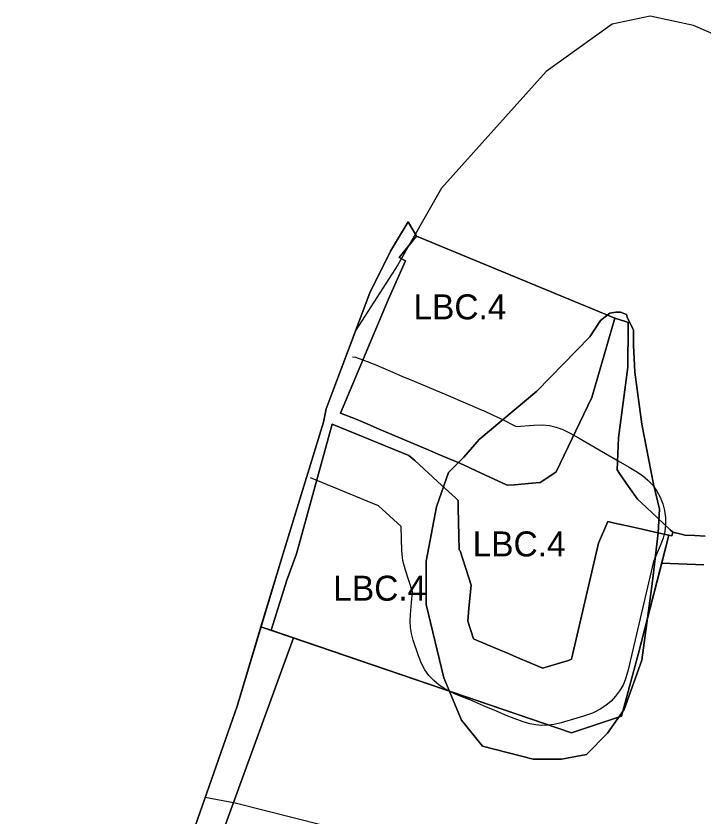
# Model space of a CAD drawing. Extents: x -555426 to -553015, y -1186745 to -1182595.
# Drawn here: x -555425.5 to -555067.9, y -1186406.3 to -1185990.3 of the extents above; entities that cross this region are included whole.
import ezdxf

# ---------------------------------------------------------------- set-up
doc = ezdxf.new("R2010")
doc.units = 0
for name, color, linetype in [('Level 12', 7, 'Continuous'), ('Level 14', 7, 'Continuous'), ('Level 7', 7, 'Continuous'), ('svahove_deformace', 7, 'Continuous'), ('USES_ID', 7, 'Continuous'), ('USES_LBC_navrh', 7, 'Continuous'), ('USES_LBC_stav', 7, 'Continuous'), ('USES_LBK_navrh', 7, 'Continuous')]:
    doc.layers.add(name, color=color, linetype=linetype)

msp = doc.modelspace()

# ---------------------------------------------------------------- linework, layer by layer
at = {"layer": 'Level 12'}
for points in [[(-555067.24, -1186260.4), (-555072.69, -1186260.16), (-555077.96, -1186259.94), (-555079.09, -1186259.62), (-555084.2, -1186258.4)], [(-555089.85, -1186274.46), (-555067.93, -1186275.38)], [(-555298.22, -1186307.56), (-555310.66, -1186348.84), (-555332.46, -1186411.11), (-555344.77, -1186450.74), (-555365.28, -1186506.04), (-555374.35, -1186523.58), (-555377.44, -1186522.92), (-555378.76, -1186526.22), (-555403.3, -1186597.68), (-555414.63, -1186645.4), (-555420.53, -1186680.78), (-555425.54, -1186725.43), (-555420.84, -1186723.67)], [(-555420.84, -1186723.67), (-555415.22, -1186721.67), (-555409.6, -1186719.66), (-555398.08, -1186648.64), (-555385.52, -1186601.65), (-555360.47, -1186527.99), (-555332.87, -1186455.38), (-555317.95, -1186413.97), (-555281.22, -1186313.35)]]:
    msp.add_lwpolyline(points, dxfattribs=at)
at = {"layer": 'Level 14'}
msp.add_lwpolyline([(-555298.22, -1186307.56), (-555136.76, -1186362.59), (-555110.73, -1186353.98), (-555101.91, -1186321.23), (-555086.13, -1186260.01), (-555084.7, -1186260.33), (-555084.2, -1186258.4), (-555085.48, -1186257.19), (-555091.92, -1186251.14), (-555097.77, -1186245.64), (-555102.5, -1186241.2), (-555107.16, -1186234.67), (-555111.88, -1186227.84), (-555113.1, -1186226.08), (-555112.35, -1186209.4), (-555107.58, -1186172.76), (-555107.3, -1186151.46), (-555107.27, -1186149.53), (-555108.76, -1186149.02), (-555114.26, -1186147.16), (-555217.36, -1186104.58), (-555221.63, -1186097.28), (-555227.21, -1186106.32), (-555230.94, -1186112.37), (-555241.55, -1186134.03), (-555264.37, -1186194.41), (-555265.72, -1186201.29), (-555286.2, -1186267.7), (-555298.22, -1186307.56)], dxfattribs=at)
at = {"layer": 'Level 7'}
msp.add_lwpolyline([(-555250.72, -1186167.24), (-555249.15, -1186167.56), (-555245.2, -1186168.87), (-555237.72, -1186171.87), (-555236.91, -1186172.21), (-555230.96, -1186174.74), (-555225.01, -1186177.29), (-555218.56, -1186179.99), (-555200.86, -1186187.48), (-555191.99, -1186191.24), (-555183.28, -1186194.95), (-555182.15, -1186195.45), (-555177.47, -1186197.61), (-555173.71, -1186199.35), (-555165.56, -1186203.42), (-555156.3, -1186202.74), (-555151.92, -1186202.63), (-555148.29, -1186202.98), (-555144.73, -1186203.77), (-555141.29, -1186205), (-555137.48, -1186206.9), (-555132.77, -1186209.62), (-555122.42, -1186215.62), (-555112.52, -1186221.34), (-555106.84, -1186224.63), (-555103.38, -1186226.63), (-555099.83, -1186228.99), (-555097.06, -1186231.36), (-555094.59, -1186234.04), (-555092.48, -1186237.01), (-555090.73, -1186240.22), (-555089.39, -1186243.61), (-555088.48, -1186247.14), (-555087.99, -1186250.75), (-555087.95, -1186254.4), (-555088.36, -1186258.03), (-555089.2, -1186261.57), (-555090.68, -1186265.57), (-555094.21, -1186273.57), (-555107.5, -1186330.65), (-555108.66, -1186334.57), (-555110.03, -1186337.79), (-555111.78, -1186340.82), (-555113.86, -1186343.64), (-555116.26, -1186346.19), (-555118.94, -1186348.44), (-555121.87, -1186350.36), (-555125.52, -1186352.2), (-555125.94, -1186352.37), (-555130.5, -1186354.02), (-555134.07, -1186355.06), (-555142.23, -1186357.46), (-555145.83, -1186358.32), (-555148.98, -1186358.72), (-555152.15, -1186358.79), (-555155.32, -1186358.52), (-555158.43, -1186357.92), (-555161.97, -1186356.83), (-555168.03, -1186354.62), (-555169.81, -1186353.92), (-555176.98, -1186350.9), (-555180.9, -1186349.26), (-555188.86, -1186345.9), (-555193.33, -1186344.02), (-555197.88, -1186342.11), (-555198.78, -1186341.73), (-555202.6, -1186339.84), (-555205.66, -1186337.83), (-555208.44, -1186335.47), (-555210.92, -1186332.79), (-555213.06, -1186329.82), (-555214.81, -1186326.62), (-555216.39, -1186322.66), (-555219.09, -1186314.48), (-555220.05, -1186310.97), (-555220.55, -1186307.89), (-555220.73, -1186304.78), (-555220.57, -1186301.14), (-555219.96, -1186294.94), (-555219.41, -1186289.33), (-555223.17, -1186278.1), (-555224.46, -1186273.05), (-555224.97, -1186268.08), (-555225.36, -1186255.41), (-555237.09, -1186244.63), (-555272.4, -1186230.19)], dxfattribs=at)
at = {"layer": 'svahove_deformace'}
for p, q in [((-555116.82, -1186144.7), (-555121.73, -1186148.37)), ((-555113.76, -1186144.08), (-555111.31, -1186144.08)), ((-555103.96, -1186175.33), (-555104.57, -1186161.24)), ((-555100.28, -1186202.29), (-555103.96, -1186175.33)), ((-555154.81, -1186185.14), (-555184.84, -1186210.26)), ((-555094.15, -1186233.54), (-555100.28, -1186202.29)), ((-555184.84, -1186210.26), (-555192.8, -1186219.45)), ((-555206.89, -1186245.18), (-555200.77, -1186227.41)), ((-555091.09, -1186246.41), (-555094.15, -1186233.54)), ((-555091.7, -1186258.66), (-555091.09, -1186246.41)), ((-555129.08, -1186373.85), (-555118.05, -1186362.82)), ((-555156.65, -1186376.3), (-555183, -1186369.56)), ((-555183, -1186369.56), (-555156.65, -1186376.3)), ((-555129.08, -1186373.85), (-555141.95, -1186376.3)), ((-555141.95, -1186376.3), (-555156.65, -1186376.3)), ((-555327.19, -1186396.06), (-555311.67, -1186398.97))]:
    msp.add_line(p, q, dxfattribs=at)
for points in [[(-554721.01, -1186449.83), (-554717.95, -1186390.39), (-554719.17, -1186364.05), (-554722.85, -1186353.02), (-554727.75, -1186346.28), (-554739.39, -1186334.64), (-554762.68, -1186319.93), (-554777.99, -1186296.65), (-554793.92, -1186260.5), (-554803.73, -1186229.86), (-554819.05, -1186205.36), (-554830.07, -1186186.97), (-554862.55, -1186143.47), (-554896.25, -1186093.23), (-554921.37, -1186069.33), (-554968.55, -1186046.05), (-555036.56, -1186011.13), (-555073.32, -1185995.19), (-555095.99, -1185990.29), (-555115.6, -1185994.58), (-555149.91, -1186019.09), (-555204.44, -1186079.75), (-555227.11, -1186119.58), (-555248.89, -1186153.45)], [(-555121.73, -1186148.37), (-555116.82, -1186144.7), (-555113.76, -1186144.08)], [(-555111.31, -1186144.08), (-555113.76, -1186144.08), (-555116.82, -1186144.7)], [(-555111.31, -1186144.08), (-555108.25, -1186145.31), (-555107.63, -1186147.15), (-555104.57, -1186153.27), (-555104.57, -1186161.24)], [(-555107.63, -1186147.15), (-555108.25, -1186145.31), (-555111.31, -1186144.08)], [(-555184.84, -1186210.26), (-555154.81, -1186185.14), (-555127.24, -1186156.95), (-555121.73, -1186148.37)], [(-555121.73, -1186148.37), (-555127.24, -1186156.95), (-555154.81, -1186185.14)], [(-555104.57, -1186161.24), (-555104.57, -1186153.27), (-555107.63, -1186147.15)], [(-555248.89, -1186153.45), (-555264.37, -1186194.41), (-555265.72, -1186201.29), (-555286.2, -1186267.7), (-555310.66, -1186348.84), (-555327.19, -1186396.06)], [(-555104.57, -1186161.24), (-555103.96, -1186175.33), (-555100.28, -1186202.29), (-555094.15, -1186233.54), (-555091.09, -1186246.41), (-555091.7, -1186258.66), (-555094.77, -1186283.78)], [(-555200.77, -1186227.41), (-555192.8, -1186219.45), (-555184.84, -1186210.26)], [(-555192.8, -1186219.45), (-555200.77, -1186227.41), (-555206.89, -1186245.18)], [(-555212.41, -1186296.04), (-555212.41, -1186273.37), (-555206.89, -1186245.18)], [(-555206.89, -1186245.18), (-555212.41, -1186273.37), (-555212.41, -1186296.04)], [(-555118.05, -1186362.82), (-555109.47, -1186350.57), (-555100.28, -1186324.83), (-555094.77, -1186283.78), (-555091.7, -1186258.66)], [(-555094.77, -1186283.78), (-555100.28, -1186324.83), (-555109.47, -1186350.57), (-555118.05, -1186362.82), (-555129.08, -1186373.85)], [(-555183, -1186369.56), (-555194.03, -1186356.08), (-555203.22, -1186334.02), (-555212.41, -1186296.04)], [(-555212.41, -1186296.04), (-555203.22, -1186334.02), (-555194.03, -1186356.08), (-555183, -1186369.56)], [(-555156.65, -1186376.3), (-555141.95, -1186376.3), (-555129.08, -1186373.85)], [(-555311.67, -1186398.97), (-555265.71, -1186410.61)]]:
    msp.add_lwpolyline(points, dxfattribs=at)
at = {"layer": 'USES_LBC_navrh'}
for p, q in [((-555226.45, -1186115.68), (-555217.36, -1186104.58)), ((-555217.36, -1186104.58), (-555114.26, -1186147.16)), ((-555223.12, -1186117.41), (-555226.45, -1186115.68)), ((-555232.18, -1186137.72), (-555223.12, -1186117.41)), ((-555256.91, -1186196.5), (-555232.18, -1186137.72)), ((-555114.26, -1186147.16), (-555123.11, -1186177.66)), ((-555123.11, -1186177.66), (-555126.25, -1186188.5)), ((-555126.25, -1186188.5), (-555144.69, -1186226.97)), ((-555248.77, -1186199.76), (-555256.91, -1186196.5)), ((-555279.68, -1186269.64), (-555261.28, -1186202.32)), ((-555261.28, -1186202.32), (-555221.4, -1186218.64)), ((-555242.74, -1186202.33), (-555248.77, -1186199.76)), ((-555236.71, -1186204.91), (-555242.74, -1186202.33)), ((-555230.2, -1186207.64), (-555236.71, -1186204.91)), ((-555212.56, -1186215.1), (-555230.2, -1186207.64)), ((-555203.72, -1186218.85), (-555212.56, -1186215.1)), ((-555221.4, -1186218.64), (-555218.31, -1186221.15)), ((-555194.89, -1186222.61), (-555203.72, -1186218.85)), ((-555218.31, -1186221.15), (-555204.2, -1186234.11)), ((-555190.05, -1186224.85), (-555194.89, -1186222.61)), ((-555185.99, -1186226.72), (-555190.05, -1186224.85)), ((-555175.06, -1186231.77), (-555185.99, -1186226.72)), ((-555146, -1186227.85), (-555153.01, -1186232.57)), ((-555144.69, -1186226.97), (-555146, -1186227.85)), ((-555170.16, -1186234.03), (-555175.06, -1186231.77)), ((-555157.32, -1186232.94), (-555166.5, -1186233.72)), ((-555153.01, -1186232.57), (-555157.32, -1186232.94)), ((-555204.2, -1186234.11), (-555197.18, -1186240.55)), ((-555166.5, -1186233.72), (-555170.16, -1186234.03)), ((-555197.18, -1186240.55), (-555195.72, -1186241.89)), ((-555195.72, -1186241.89), (-555195.64, -1186245.84)), ((-555195.64, -1186245.84), (-555195.22, -1186267.63)), ((-555122.79, -1186264.03), (-555117.88, -1186252.9)), ((-555117.88, -1186252.9), (-555114.53, -1186253.65)), ((-555114.53, -1186253.65), (-555107.79, -1186255.16)), ((-555107.79, -1186255.16), (-555100.06, -1186256.89)), ((-555100.06, -1186256.89), (-555093.4, -1186258.38)), ((-555093.4, -1186258.38), (-555086.13, -1186260.01)), ((-555086.13, -1186260.01), (-555089.85, -1186274.46)), ((-555136.85, -1186324.41), (-555122.79, -1186264.03)), ((-555284.72, -1186283.32), (-555279.68, -1186269.64)), ((-555195.22, -1186267.63), (-555194.7, -1186268.11)), ((-555194.7, -1186268.11), (-555188.93, -1186285.88)), ((-555292.95, -1186309.36), (-555284.72, -1186283.32)), ((-555188.93, -1186285.88), (-555190.1, -1186297.86)), ((-555190.1, -1186297.86), (-555190.76, -1186304.59)), ((-555190.76, -1186304.59), (-555187.71, -1186313.84)), ((-555281.22, -1186313.35), (-555292.95, -1186309.36)), ((-555136.76, -1186362.59), (-555281.22, -1186313.35)), ((-555187.71, -1186313.84), (-555186.26, -1186314.45)), ((-555186.26, -1186314.45), (-555181.71, -1186316.36)), ((-555181.71, -1186316.36), (-555177.22, -1186318.25)), ((-555177.22, -1186318.25), (-555169.27, -1186321.6)), ((-555169.27, -1186321.6), (-555165.36, -1186323.24)), ((-555165.36, -1186323.24), (-555157.95, -1186326.36)), ((-555138.36, -1186325.06), (-555136.85, -1186324.41)), ((-555157.95, -1186326.36), (-555151.71, -1186328.98)), ((-555150.68, -1186328.68), (-555142.52, -1186326.28)), ((-555142.52, -1186326.28), (-555138.36, -1186325.06)), ((-555151.71, -1186328.98), (-555150.68, -1186328.68))]:
    msp.add_line(p, q, dxfattribs=at)
for points in [[(-555089.85, -1186274.46), (-555101.91, -1186321.23), (-555110.73, -1186353.98), (-555136.76, -1186362.59)], [(-555089.85, -1186274.46), (-555089.85, -1186274.46)]]:
    msp.add_lwpolyline(points, dxfattribs=at)
at = {"layer": 'USES_LBC_stav'}
for p, q in [((-555217.36, -1186104.58), (-555226.45, -1186115.68)), ((-555226.45, -1186115.68), (-555223.12, -1186117.41)), ((-555223.12, -1186117.41), (-555232.18, -1186137.72)), ((-555232.18, -1186137.72), (-555256.91, -1186196.5)), ((-555123.11, -1186177.66), (-555114.26, -1186147.16)), ((-555126.25, -1186188.5), (-555123.11, -1186177.66)), ((-555144.69, -1186226.97), (-555126.25, -1186188.5)), ((-555256.91, -1186196.5), (-555248.77, -1186199.76)), ((-555261.28, -1186202.32), (-555279.68, -1186269.64)), ((-555221.4, -1186218.64), (-555261.28, -1186202.32)), ((-555248.77, -1186199.76), (-555242.74, -1186202.33)), ((-555242.74, -1186202.33), (-555236.71, -1186204.91)), ((-555236.71, -1186204.91), (-555230.2, -1186207.64)), ((-555230.2, -1186207.64), (-555212.56, -1186215.1)), ((-555212.56, -1186215.1), (-555203.72, -1186218.85)), ((-555218.31, -1186221.15), (-555221.4, -1186218.64)), ((-555203.72, -1186218.85), (-555194.89, -1186222.61)), ((-555204.2, -1186234.11), (-555218.31, -1186221.15)), ((-555194.89, -1186222.61), (-555190.05, -1186224.85)), ((-555190.05, -1186224.85), (-555185.99, -1186226.72)), ((-555185.99, -1186226.72), (-555175.06, -1186231.77)), ((-555153.01, -1186232.57), (-555146, -1186227.85)), ((-555146, -1186227.85), (-555144.69, -1186226.97)), ((-555175.06, -1186231.77), (-555170.16, -1186234.03)), ((-555166.5, -1186233.72), (-555157.32, -1186232.94)), ((-555157.32, -1186232.94), (-555153.01, -1186232.57)), ((-555197.18, -1186240.55), (-555204.2, -1186234.11)), ((-555170.16, -1186234.03), (-555166.5, -1186233.72)), ((-555195.72, -1186241.89), (-555197.18, -1186240.55)), ((-555195.64, -1186245.84), (-555195.72, -1186241.89)), ((-555195.22, -1186267.63), (-555195.64, -1186245.84)), ((-555117.88, -1186252.9), (-555122.79, -1186264.03)), ((-555114.53, -1186253.65), (-555117.88, -1186252.9)), ((-555107.79, -1186255.16), (-555114.53, -1186253.65)), ((-555100.06, -1186256.89), (-555107.79, -1186255.16)), ((-555093.4, -1186258.38), (-555100.06, -1186256.89)), ((-555086.13, -1186260.01), (-555093.4, -1186258.38)), ((-555084.7, -1186260.33), (-555086.13, -1186260.01)), ((-555084.2, -1186258.4), (-555084.7, -1186260.33)), ((-555122.79, -1186264.03), (-555136.85, -1186324.41)), ((-555279.68, -1186269.64), (-555284.72, -1186283.32)), ((-555194.7, -1186268.11), (-555195.22, -1186267.63)), ((-555188.93, -1186285.88), (-555194.7, -1186268.11)), ((-555284.72, -1186283.32), (-555292.95, -1186309.36)), ((-555190.1, -1186297.86), (-555188.93, -1186285.88)), ((-555190.76, -1186304.59), (-555190.1, -1186297.86)), ((-555187.71, -1186313.84), (-555190.76, -1186304.59)), ((-555186.26, -1186314.45), (-555187.71, -1186313.84)), ((-555181.71, -1186316.36), (-555186.26, -1186314.45)), ((-555177.22, -1186318.25), (-555181.71, -1186316.36)), ((-555169.27, -1186321.6), (-555177.22, -1186318.25)), ((-555165.36, -1186323.24), (-555169.27, -1186321.6)), ((-555157.95, -1186326.36), (-555165.36, -1186323.24)), ((-555136.85, -1186324.41), (-555138.36, -1186325.06)), ((-555151.71, -1186328.98), (-555157.95, -1186326.36)), ((-555142.52, -1186326.28), (-555150.68, -1186328.68)), ((-555138.36, -1186325.06), (-555142.52, -1186326.28)), ((-555150.68, -1186328.68), (-555151.71, -1186328.98))]:
    msp.add_line(p, q, dxfattribs=at)
for points in [[(-555292.95, -1186309.36), (-555298.22, -1186307.56), (-555286.2, -1186267.7), (-555265.72, -1186201.29), (-555264.37, -1186194.41), (-555241.55, -1186134.03), (-555230.94, -1186112.37), (-555227.21, -1186106.32), (-555221.63, -1186097.28), (-555217.36, -1186104.58)], [(-555114.26, -1186147.16), (-555108.76, -1186149.02), (-555107.27, -1186149.53), (-555107.3, -1186151.46), (-555107.58, -1186172.76), (-555112.35, -1186209.4), (-555113.1, -1186226.08), (-555111.88, -1186227.84), (-555107.16, -1186234.67), (-555102.5, -1186241.2), (-555097.77, -1186245.64), (-555091.92, -1186251.14), (-555085.48, -1186257.19), (-555084.2, -1186258.4)]]:
    msp.add_lwpolyline(points, dxfattribs=at)
at = {"layer": 'USES_LBK_navrh'}
for p, q in [((-555089.85, -1186274.46), (-555086.13, -1186260.01)), ((-555086.13, -1186260.01), (-555084.7, -1186260.33)), ((-555084.7, -1186260.33), (-555084.2, -1186258.4)), ((-555084.2, -1186258.4), (-555079.09, -1186259.62)), ((-555079.09, -1186259.62), (-555077.96, -1186259.94)), ((-555067.93, -1186275.38), (-555089.85, -1186274.46)), ((-555298.22, -1186307.56), (-555292.95, -1186309.36)), ((-555292.95, -1186309.36), (-555281.22, -1186313.35)), ((-555281.22, -1186313.35), (-555317.95, -1186413.97))]:
    msp.add_line(p, q, dxfattribs=at)
for points in [[(-555077.96, -1186259.94), (-555072.69, -1186260.16), (-555067.24, -1186260.4)], [(-555374.35, -1186523.58), (-555365.28, -1186506.04), (-555344.77, -1186450.74), (-555332.46, -1186411.11), (-555310.66, -1186348.84), (-555298.22, -1186307.56)]]:
    msp.add_lwpolyline(points, dxfattribs=at)

# ---------------------------------------------------------------- texts
at = {"layer": 'USES_ID'}
for p in [(-555218.95, -1186147.86), (-555188.18, -1186271), (-555260.62, -1186293.99)]:
    msp.add_text('LBC.4', height=13, dxfattribs=at).set_placement(p)

doc.saveas('drawing.dxf')
